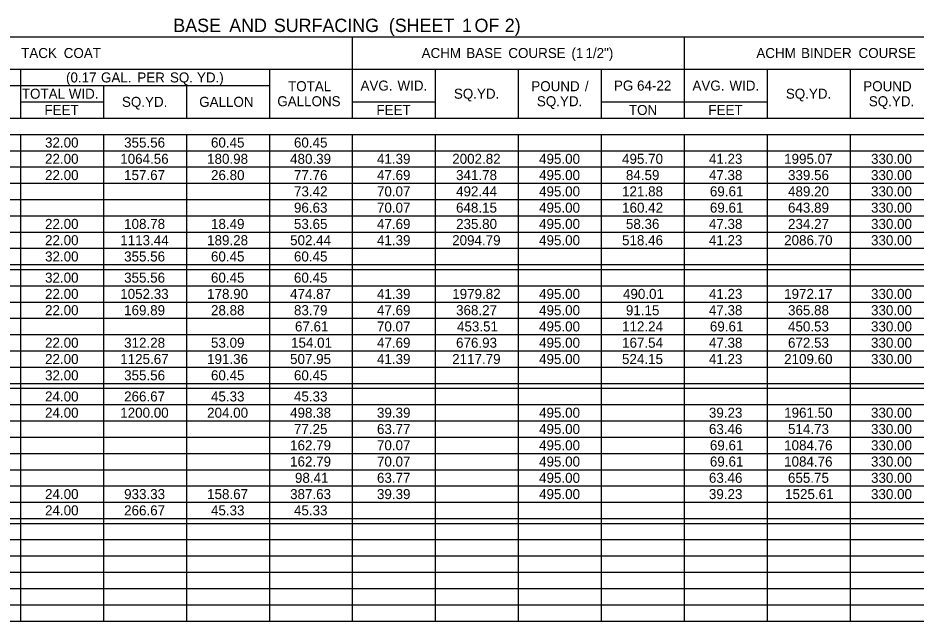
# Model space of a CAD drawing. Extents: x 977434 to 989596, y 1525697 to 1528336.
# Drawn here: x 983226 to 983656.5, y 1527821 to 1528110.1 of the extents above; entities that cross this region are included whole.
import ezdxf

# ---------------------------------------------------------------- set-up
doc = ezdxf.new("R2010")
doc.units = 0
doc.layers.add('Default', color=7, linetype='Continuous')

msp = doc.modelspace()

# ---------------------------------------------------------------- linework, layer by layer
at = {"layer": 'Default'}
for p, q in [((982704.74, 1528101.06), (984062.72, 1528101.06)), ((983386.46, 1528062.06), (983386.46, 1528101.06)), ((983545.58, 1528085.46), (983545.58, 1528101.06)), ((983545.58, 1528062.06), (983545.58, 1528101.06)), ((983028.44, 1528085.46), (984062.72, 1528085.46)), ((983227.34, 1528062.06), (983227.34, 1528085.46)), ((983346.68, 1528062.06), (983346.68, 1528085.46)), ((983426.24, 1528062.06), (983426.24, 1528085.46)), ((983466.02, 1528062.06), (983466.02, 1528085.46)), ((983505.8, 1528062.06), (983505.8, 1528085.46)), ((983585.36, 1528062.06), (983585.36, 1528085.46)), ((983625.14, 1528062.06), (983625.14, 1528085.46)), ((983108, 1528077.66), (983346.68, 1528077.66)), ((983267.12, 1528062.06), (983267.12, 1528077.66)), ((983306.9, 1528062.06), (983306.9, 1528077.66)), ((983227.34, 1528069.86), (983267.12, 1528069.86)), ((983267.12, 1528062.06), (983267.12, 1528069.86)), ((983386.46, 1528069.86), (983426.24, 1528069.86)), ((983426.24, 1528062.06), (983426.24, 1528069.86)), ((983505.8, 1528069.86), (983585.36, 1528069.86)), ((983585.36, 1528062.06), (983585.36, 1528069.86)), ((982704.74, 1528062.06), (984062.72, 1528062.06)), ((983147.78, 1528062.06), (983267.12, 1528062.06)), ((983267.12, 1528062.06), (983306.9, 1528062.06)), ((983306.9, 1528062.06), (983426.24, 1528062.06)), ((983426.24, 1528062.06), (983585.36, 1528062.06)), ((983585.36, 1528062.06), (983744.48, 1528062.06)), ((982704.74, 1528054.26), (984062.72, 1528054.26)), ((983227.34, 1527821.04), (983227.34, 1528054.26)), ((983227.34, 1527821.04), (983227.34, 1528054.26)), ((983267.12, 1527821.04), (983267.12, 1528054.26)), ((983267.12, 1527821.04), (983267.12, 1528054.26)), ((983306.9, 1527821.04), (983306.9, 1528054.26)), ((983306.9, 1527821.04), (983306.9, 1528054.26)), ((983346.68, 1527821.04), (983346.68, 1528054.26)), ((983346.68, 1527821.04), (983346.68, 1528054.26)), ((983386.46, 1527821.04), (983386.46, 1528054.26)), ((983386.46, 1527821.04), (983386.46, 1528054.26)), ((983426.24, 1527821.04), (983426.24, 1528054.26)), ((983426.24, 1527821.04), (983426.24, 1528054.26)), ((983466.02, 1527821.04), (983466.02, 1528054.26)), ((983466.02, 1527821.04), (983466.02, 1528054.26)), ((983505.8, 1527821.04), (983505.8, 1528054.26)), ((983505.8, 1527821.04), (983505.8, 1528054.26)), ((983545.58, 1527821.04), (983545.58, 1528054.26)), ((983545.58, 1527821.04), (983545.58, 1528054.26)), ((983585.36, 1527821.04), (983585.36, 1528054.26)), ((983585.36, 1527821.04), (983585.36, 1528054.26)), ((983625.14, 1527821.04), (983625.14, 1528054.26)), ((983625.14, 1527821.04), (983625.14, 1528054.26)), ((982704.74, 1528046.46), (984062.72, 1528046.46)), ((982704.74, 1528038.66), (984062.72, 1528038.66)), ((982704.74, 1528030.86), (984062.72, 1528030.86)), ((982704.74, 1528023.06), (984062.72, 1528023.06)), ((982704.74, 1528015.26), (984062.72, 1528015.26)), ((982704.74, 1528007.46), (984062.72, 1528007.46)), ((982704.74, 1527999.66), (984062.72, 1527999.66)), ((982704.74, 1527991.86), (984062.72, 1527991.86)), ((982704.74, 1527989.52), (984062.72, 1527989.52)), ((982704.74, 1527981.72), (984062.72, 1527981.72)), ((982704.74, 1527973.92), (984062.72, 1527973.92)), ((982704.74, 1527966.12), (984062.72, 1527966.12)), ((982704.74, 1527958.32), (984062.72, 1527958.32)), ((982704.74, 1527950.52), (984062.72, 1527950.52)), ((982704.74, 1527942.72), (984062.72, 1527942.72)), ((982704.74, 1527934.92), (984062.72, 1527934.92)), ((982704.74, 1527932.58), (984062.72, 1527932.58)), ((982704.74, 1527924.78), (984062.72, 1527924.78)), ((982704.74, 1527916.98), (984062.72, 1527916.98)), ((982704.74, 1527909.18), (984062.72, 1527909.18)), ((982704.74, 1527901.38), (984062.72, 1527901.38)), ((982704.74, 1527893.58), (984062.72, 1527893.58)), ((982704.74, 1527885.78), (984062.72, 1527885.78)), ((982704.74, 1527877.98), (984062.72, 1527877.98)), ((982704.74, 1527870.18), (984062.72, 1527870.18)), ((982704.74, 1527867.84), (984062.72, 1527867.84)), ((982704.74, 1527860.04), (984062.72, 1527860.04)), ((982704.74, 1527852.24), (984062.72, 1527852.24)), ((982704.74, 1527844.44), (984062.72, 1527844.44)), ((982704.74, 1527836.64), (984062.72, 1527836.64)), ((982704.74, 1527828.84), (984062.72, 1527828.84)), ((982704.74, 1527821.04), (984062.72, 1527821.04)), ((983147.78, 1527821.04), (983227.34, 1527821.04)), ((983227.34, 1527821.04), (983267.12, 1527821.04)), ((983267.12, 1527821.04), (983386.46, 1527821.04)), ((983386.46, 1527821.04), (983903.6, 1527821.04))]:
    msp.add_line(p, q, dxfattribs=at)

# ---------------------------------------------------------------- texts
for s, height, p in [('BASE', 6.4, (983300.49, 1528103.32)), (' AND', 6.4, (983324.9, 1528103.32)), (' SURFACING', 6.4, (983346.31, 1528103.32)), (' (SHEET', 6.4, (983401.42, 1528103.32)), (' 1', 6.4, (983436.51, 1528103.32)), (' OF', 6.4, (983442.51, 1528103.32)), (' 2)', 6.4, (983457, 1528103.32)), ('TACK', 4.8, (983227.56, 1528090.86)), (' COAT', 4.8, (983246.18, 1528090.86)), ('ACHM', 4.8, (983419.51, 1528090.86)), (' BASE', 4.8, (983439.15, 1528090.86)), (' COURSE', 4.8, (983459.32, 1528090.86)), (' (1', 4.8, (983489.55, 1528090.86)), (' 1/2")', 4.8, (983496.28, 1528090.86)), ('ACHM', 4.8, (983579.99, 1528090.86)), (' BINDER', 4.8, (983599.63, 1528090.86)), (' COURSE', 4.8, (983627.17, 1528090.86)), ('(0.17', 4.8, (983249.06, 1528079.16)), (' GAL.', 4.8, (983264.04, 1528079.16)), (' PER', 4.8, (983281.46, 1528079.16)), (' SQ.', 4.8, (983297.08, 1528079.16)), (' YD.)', 4.8, (983310.04, 1528079.16)), ('TOTAL', 4.8, (983355.49, 1528074.96)), ('AVG.', 4.8, (983390.23, 1528075.26)), (' WID.', 4.8, (983406.17, 1528075.26)), ('POUND', 4.8, (983472.1, 1528074.96)), (' /', 4.8, (983495.99, 1528074.96)), ('PG', 4.8, (983511.71, 1528075.26)), (' 64-22', 4.8, (983521, 1528075.26)), ('AVG.', 4.8, (983549.35, 1528075.26)), (' WID.', 4.8, (983565.29, 1528075.26)), ('POUND', 4.8, (983631.22, 1528074.96)), ('TOTAL WID.', 4.8, (983227.9, 1528071.36)), ('GALLONS', 4.8, (983350.34, 1528067.76)), ('SQ.YD.', 4.8, (983434.99, 1528071.36)), ('SQ.YD.', 4.8, (983474.77, 1528067.76)), ('SQ.YD.', 4.8, (983594.11, 1528071.36)), ('SQ.YD.', 4.8, (983633.89, 1528067.76)), ('FEET', 4.8, (983238.73, 1528063.56)), ('SQ.YD.', 4.8, (983275.87, 1528067.46)), ('GALLON', 4.8, (983312.9, 1528067.46)), ('FEET', 4.8, (983397.85, 1528063.56)), ('TON', 4.8, (983518.88, 1528063.56)), ('FEET', 4.8, (983556.97, 1528063.56)), ('32.00', 4.8, (983239, 1528047.96)), ('355.56', 4.8, (983276.91, 1528047.96)), ('60.45', 4.8, (983318.54, 1528047.96)), ('60.45', 4.8, (983358.32, 1528047.96)), ('22.00', 4.8, (983239, 1528040.16)), ('1064.56', 4.8, (983275.05, 1528040.16)), ('180.98', 4.8, (983316.69, 1528040.16)), ('480.39', 4.8, (983356.47, 1528040.16)), ('41.39', 4.8, (983398.11, 1528040.16)), ('2002.82', 4.8, (983434.19, 1528040.16)), ('495.00', 4.8, (983475.82, 1528040.16)), ('495.70', 4.8, (983515.6, 1528040.16)), ('41.23', 4.8, (983557.23, 1528040.16)), ('1995.07', 4.8, (983593.29, 1528040.16)), ('330.00', 4.8, (983634.94, 1528040.16)), ('22.00', 4.8, (983239, 1528032.36)), ('157.67', 4.8, (983276.91, 1528032.36)), ('26.80', 4.8, (983318.56, 1528032.36)), ('77.76', 4.8, (983358.33, 1528032.36)), ('47.69', 4.8, (983398.11, 1528032.36)), ('341.78', 4.8, (983436.03, 1528032.36)), ('495.00', 4.8, (983475.82, 1528032.36)), ('84.59', 4.8, (983517.45, 1528032.36)), ('47.38', 4.8, (983557.23, 1528032.36)), ('339.56', 4.8, (983595.15, 1528032.36)), ('330.00', 4.8, (983634.94, 1528032.36)), ('73.42', 4.8, (983358.36, 1528024.56)), ('70.07', 4.8, (983398.11, 1528024.56)), ('492.44', 4.8, (983436.04, 1528024.56)), ('495.00', 4.8, (983475.82, 1528024.56)), ('121.88', 4.8, (983515.59, 1528024.56)), ('69.61', 4.8, (983557.7, 1528024.56)), ('489.20', 4.8, (983595.16, 1528024.56)), ('330.00', 4.8, (983634.94, 1528024.56)), ('96.63', 4.8, (983358.33, 1528016.76)), ('70.07', 4.8, (983398.11, 1528016.76)), ('648.15', 4.8, (983436.01, 1528016.76)), ('495.00', 4.8, (983475.82, 1528016.76)), ('160.42', 4.8, (983515.62, 1528016.76)), ('69.61', 4.8, (983557.7, 1528016.76)), ('643.89', 4.8, (983595.15, 1528016.76)), ('330.00', 4.8, (983634.94, 1528016.76)), ('22.00', 4.8, (983239, 1528008.96)), ('108.78', 4.8, (983276.91, 1528008.96)), ('18.49', 4.8, (983318.55, 1528008.96)), ('53.65', 4.8, (983358.32, 1528008.96)), ('47.69', 4.8, (983398.11, 1528008.96)), ('235.80', 4.8, (983436.04, 1528008.96)), ('495.00', 4.8, (983475.82, 1528008.96)), ('58.36', 4.8, (983517.45, 1528008.96)), ('47.38', 4.8, (983557.23, 1528008.96)), ('234.27', 4.8, (983595.15, 1528008.96)), ('330.00', 4.8, (983634.94, 1528008.96)), ('22.00', 4.8, (983239, 1528001.16)), ('1113.44', 4.8, (983275.06, 1528001.16)), ('189.28', 4.8, (983316.69, 1528001.16)), ('502.44', 4.8, (983356.48, 1528001.16)), ('41.39', 4.8, (983398.11, 1528001.16)), ('2094.79', 4.8, (983434.16, 1528001.16)), ('495.00', 4.8, (983475.82, 1528001.16)), ('518.46', 4.8, (983515.59, 1528001.16)), ('41.23', 4.8, (983557.23, 1528001.16)), ('2086.70', 4.8, (983593.3, 1528001.16)), ('330.00', 4.8, (983634.94, 1528001.16)), ('32.00', 4.8, (983239, 1527993.36)), ('355.56', 4.8, (983276.91, 1527993.36)), ('60.45', 4.8, (983318.54, 1527993.36)), ('60.45', 4.8, (983358.32, 1527993.36)), ('32.00', 4.8, (983239, 1527983.22)), ('355.56', 4.8, (983276.91, 1527983.22)), ('60.45', 4.8, (983318.54, 1527983.22)), ('60.45', 4.8, (983358.32, 1527983.22)), ('22.00', 4.8, (983239, 1527975.42)), ('1052.33', 4.8, (983275.05, 1527975.42)), ('178.90', 4.8, (983316.7, 1527975.42)), ('474.87', 4.8, (983356.47, 1527975.42)), ('41.39', 4.8, (983398.11, 1527975.42)), ('1979.82', 4.8, (983434.19, 1527975.42)), ('495.00', 4.8, (983475.82, 1527975.42)), ('490.01', 4.8, (983516.05, 1527975.42)), ('41.23', 4.8, (983557.23, 1527975.42)), ('1972.17', 4.8, (983593.29, 1527975.42)), ('330.00', 4.8, (983634.94, 1527975.42)), ('22.00', 4.8, (983239, 1527967.62)), ('169.89', 4.8, (983276.91, 1527967.62)), ('28.88', 4.8, (983318.55, 1527967.62)), ('83.79', 4.8, (983358.33, 1527967.62)), ('47.69', 4.8, (983398.11, 1527967.62)), ('368.27', 4.8, (983436.03, 1527967.62)), ('495.00', 4.8, (983475.82, 1527967.62)), ('91.15', 4.8, (983517.44, 1527967.62)), ('47.38', 4.8, (983557.23, 1527967.62)), ('365.88', 4.8, (983595.15, 1527967.62)), ('330.00', 4.8, (983634.94, 1527967.62)), ('67.61', 4.8, (983358.8, 1527959.82)), ('70.07', 4.8, (983398.11, 1527959.82)), ('453.51', 4.8, (983436.49, 1527959.82)), ('495.00', 4.8, (983475.82, 1527959.82)), ('112.24', 4.8, (983515.6, 1527959.82)), ('69.61', 4.8, (983557.7, 1527959.82)), ('450.53', 4.8, (983595.15, 1527959.82)), ('330.00', 4.8, (983634.94, 1527959.82)), ('22.00', 4.8, (983239, 1527952.02)), ('312.28', 4.8, (983276.91, 1527952.02)), ('53.09', 4.8, (983318.55, 1527952.02)), ('154.01', 4.8, (983356.93, 1527952.02)), ('47.69', 4.8, (983398.11, 1527952.02)), ('676.93', 4.8, (983436.03, 1527952.02)), ('495.00', 4.8, (983475.82, 1527952.02)), ('167.54', 4.8, (983515.6, 1527952.02)), ('47.38', 4.8, (983557.23, 1527952.02)), ('672.53', 4.8, (983595.15, 1527952.02)), ('330.00', 4.8, (983634.94, 1527952.02)), ('22.00', 4.8, (983239, 1527944.22)), ('1125.67', 4.8, (983275.05, 1527944.22)), ('191.36', 4.8, (983316.69, 1527944.22)), ('507.95', 4.8, (983356.45, 1527944.22)), ('41.39', 4.8, (983398.11, 1527944.22)), ('2117.79', 4.8, (983434.16, 1527944.22)), ('495.00', 4.8, (983475.82, 1527944.22)), ('524.15', 4.8, (983515.57, 1527944.22)), ('41.23', 4.8, (983557.23, 1527944.22)), ('2109.60', 4.8, (983593.3, 1527944.22)), ('330.00', 4.8, (983634.94, 1527944.22)), ('32.00', 4.8, (983239, 1527936.42)), ('355.56', 4.8, (983276.91, 1527936.42)), ('60.45', 4.8, (983318.54, 1527936.42)), ('60.45', 4.8, (983358.32, 1527936.42)), ('24.00', 4.8, (983239, 1527926.28)), ('266.67', 4.8, (983276.91, 1527926.28)), ('45.33', 4.8, (983318.55, 1527926.28)), ('45.33', 4.8, (983358.33, 1527926.28)), ('24.00', 4.8, (983239, 1527918.48)), ('1200.00', 4.8, (983275.06, 1527918.48)), ('204.00', 4.8, (983316.7, 1527918.48)), ('498.38', 4.8, (983356.47, 1527918.48)), ('39.39', 4.8, (983398.11, 1527918.48)), ('495.00', 4.8, (983475.82, 1527918.48)), ('39.23', 4.8, (983557.23, 1527918.48)), ('1961.50', 4.8, (983593.3, 1527918.48)), ('330.00', 4.8, (983634.94, 1527918.48)), ('77.25', 4.8, (983358.32, 1527910.68)), ('63.77', 4.8, (983398.11, 1527910.68)), ('495.00', 4.8, (983475.82, 1527910.68)), ('63.46', 4.8, (983557.23, 1527910.68)), ('514.73', 4.8, (983595.15, 1527910.68)), ('330.00', 4.8, (983634.94, 1527910.68)), ('162.79', 4.8, (983356.47, 1527902.88)), ('70.07', 4.8, (983398.11, 1527902.88)), ('495.00', 4.8, (983475.82, 1527902.88)), ('69.61', 4.8, (983557.7, 1527902.88)), ('1084.76', 4.8, (983593.29, 1527902.88)), ('330.00', 4.8, (983634.94, 1527902.88)), ('162.79', 4.8, (983356.47, 1527895.08)), ('70.07', 4.8, (983398.11, 1527895.08)), ('495.00', 4.8, (983475.82, 1527895.08)), ('69.61', 4.8, (983557.7, 1527895.08)), ('1084.76', 4.8, (983593.29, 1527895.08)), ('330.00', 4.8, (983634.94, 1527895.08)), ('98.41', 4.8, (983358.8, 1527887.28)), ('63.77', 4.8, (983398.11, 1527887.28)), ('495.00', 4.8, (983475.82, 1527887.28)), ('63.46', 4.8, (983557.23, 1527887.28)), ('655.75', 4.8, (983595.13, 1527887.28)), ('330.00', 4.8, (983634.94, 1527887.28)), ('24.00', 4.8, (983239, 1527879.48)), ('933.33', 4.8, (983276.91, 1527879.48)), ('158.67', 4.8, (983316.69, 1527879.48)), ('387.63', 4.8, (983356.47, 1527879.48)), ('39.39', 4.8, (983398.11, 1527879.48)), ('495.00', 4.8, (983475.82, 1527879.48)), ('39.23', 4.8, (983557.23, 1527879.48)), ('1525.61', 4.8, (983593.75, 1527879.48)), ('330.00', 4.8, (983634.94, 1527879.48)), ('24.00', 4.8, (983239, 1527871.68)), ('266.67', 4.8, (983276.91, 1527871.68)), ('45.33', 4.8, (983318.55, 1527871.68)), ('45.33', 4.8, (983358.33, 1527871.68))]:
    msp.add_text(s, height=height, dxfattribs=at).set_placement(p)

doc.saveas('drawing.dxf')
